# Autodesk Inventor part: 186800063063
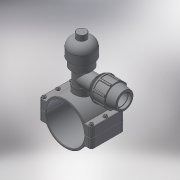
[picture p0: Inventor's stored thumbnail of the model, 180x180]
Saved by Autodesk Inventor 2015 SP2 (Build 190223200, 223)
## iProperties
Created: 2017-05
Part Number: 186800063063
Material: Generic
Description: PLASSON MECHANICAL TAPPING VALVE 63-63
Document SubType Name: Modeling
Designer: KIM
Density: 1 g/cm^3
Appearance: Default
Author: KIM
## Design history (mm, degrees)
derived "18680.ipt"
feature "Solid1::18680.ipt"
feature "Solid2::18680.ipt"
tag "TaggingFeature1"
body "Solid1"
other parameters: "d0" = 78.75, "d1" = 116, "d2" = 31.5, "d3" = 63, "d4" = 84, "d5" = 0, "d6" = 5.8, "d7" = 116, "d8" = 0.1, "d10" = 0, "d11" = 0.63, "d14" = 58.2985, "d20" = 0.63, "d23" = 0.63, "d37" = 8, "d38" = 39.5, "d39" = 0, "d40" = 3, "d41" = 5, "d42" = 0, "d43" = 6, "d44" = 3, "d45" = 0, "d46" = 0.63, "d51" = 61, "d52" = 44.845, "d53" = 21, "d54" = 0, "d57" = 0, "d58" = 68.04, "d60" = 0, "d63" = 8, "d66" = 68, "d67" = 63, "d68" = 16.66667, "d70" = 113, "d71" = 84.75, "d72" = 2.85714, "d73" = 90.4, "d74" = 120 deg, "d75" = 81.9, "d76" = 10 deg, "d77" = 101.7, "d80" = 40.95, "d82" = 11, "d87" = 28.57143, "d90" = 105.09, "d91" = 35 deg, "d92" = 17.5 deg, "d94" = 0, "d96" = 360 deg, "d98" = 1.26, "d99" = 121, "d100" = 50.85, "d101" = 135 deg, "d102" = 2.26, "d105" = 5.65, "d106" = 0, "d107" = 0.1, "d109" = 58.2985, "d112" = 34.28571, "d113" = 6.66667, "d116" = 0, "d121" = 53.814, "d122" = 89.69, "d123" = 76.2365, "d124" = 45 deg, "d125" = 216, "d127" = 144, "d128" = 1, "d_" = 63, "G_" = 44.845, "A_" = 61, "L_" = 116, "L_1" = 84, "l_2" = 21, "d_1" = 63, "E_" = 113
